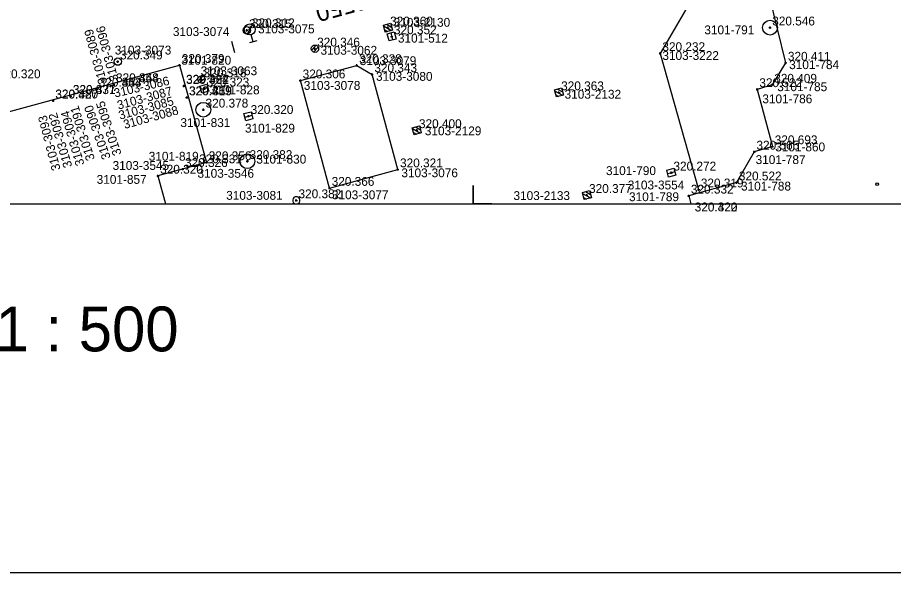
# Model space of a CAD drawing. Extents: x -821875 to -821475, y -1070280 to -1069975.
# Drawn here: x -821680.9 to -821621.5, y -1070275 to -1070237.4 of the extents above; entities that cross this region are included whole.
import ezdxf

# ---------------------------------------------------------------- set-up
doc = ezdxf.new("R2010")
doc.units = 0
for name, color, linetype in [('Vrstva 1', 7, 'Continuous'), ('Vrstva 17', 7, 'Continuous'), ('Vrstva 23', 7, 'Continuous'), ('Vrstva 3', 7, 'Continuous'), ('Vrstva 36', 7, 'Continuous'), ('Vrstva 41', 7, 'Continuous'), ('Vrstva 43', 7, 'Continuous'), ('Vrstva 47', 7, 'Continuous'), ('Vrstva 52', 7, 'Continuous'), ('Vrstva 59', 7, 'Continuous'), ('Vrstva 6', 7, 'Continuous'), ('Vrstva 60', 7, 'Continuous'), ('Vrstva 61', 7, 'Continuous'), ('Vrstva 63', 7, 'Continuous')]:
    doc.layers.add(name, color=color, linetype=linetype)

# ---------------------------------------------------------------- blocks, each defined once
blk = doc.blocks.new('BOD')
at = {"layer": 'Vrstva 3'}
for p, q in [((-0.15, 0), (0.15, 0)), ((0, -0.15), (0, 0.15))]:
    blk.add_line(p, q, dxfattribs=at)

msp = doc.modelspace()

# ---------------------------------------------------------------- linework, layer by layer
at = {"layer": 'Vrstva 1'}
for points in [[(-821475, -1069975), (-821875, -1069975), (-821875, -1070275), (-821475, -1070275)], [(-821500, -1070000), (-821850, -1070000), (-821850, -1070250), (-821500, -1070250)], [(-821500, -1070000), (-821850, -1070000), (-821850, -1070250), (-821500, -1070250)]]:
    msp.add_lwpolyline(points, close=True, dxfattribs=at)
for points in [[(-821650, -1070250), (-821650, -1070248.75), (-821650, -1070250)], [(-821651.25, -1070250), (-821650, -1070250)], [(-821650, -1070250), (-821648.75, -1070250), (-821650, -1070250)]]:
    msp.add_lwpolyline(points, dxfattribs=at)
at = {"layer": 'Vrstva 17'}
for p, q in [((-821633.688, -1070233.585), (-821637.314, -1070239.784)), ((-821637.314, -1070239.784), (-821634.707, -1070249.031))]:
    msp.add_line(p, q, dxfattribs=at)
at = {"layer": 'Vrstva 23'}
for p, q in [((-821661.733, -1070241.633), (-821657.903, -1070240.599)), ((-821657.903, -1070240.599), (-821656.866, -1070241.213)), ((-821659.762, -1070248.922), (-821661.733, -1070241.633)), ((-821655.121, -1070247.667), (-821656.866, -1070241.213)), ((-821659.762, -1070248.922), (-821655.121, -1070247.667))]:
    msp.add_line(p, q, dxfattribs=at)
for points in [[(-821618.032, -1070237.847), (-821619.404, -1070232.915), (-821629.947, -1070235.793), (-821628.796, -1070240.434), (-821629.722, -1070241.929), (-821630.734, -1070242.226), (-821629.687, -1070246.101), (-821630.928, -1070246.466), (-821632.123, -1070248.555), (-821635.379, -1070249.449), (-821635.229, -1070250)], [(-821684.746, -1070244.201), (-821684.641, -1070244.592), (-821669.935, -1070240.588), (-821668.108, -1070247.182)], [(-821668.108, -1070247.182), (-821671.404, -1070248.095), (-821670.899, -1070250)]]:
    msp.add_lwpolyline(points, dxfattribs=at)
at = {"layer": 'Vrstva 36'}
for p, q in [((-821656.086, -1070237.924), (-821655.544, -1070238.236)), ((-821655.883, -1070237.81), (-821655.548, -1070238.004)), ((-821656.013, -1070238.196), (-821655.817, -1070238.31)), ((-821660.978, -1070239.563), (-821660.654, -1070239.24)), ((-821660.848, -1070239.698), (-821660.52, -1070239.37)), ((-821668.68, -1070241.65), (-821668.356, -1070241.327)), ((-821668.55, -1070241.785), (-821668.222, -1070241.458)), ((-821644.476, -1070242.318), (-821643.934, -1070242.63)), ((-821644.273, -1070242.204), (-821643.938, -1070242.398)), ((-821644.403, -1070242.59), (-821644.207, -1070242.704)), ((-821654.128, -1070244.886), (-821653.586, -1070245.198)), ((-821654.055, -1070245.158), (-821653.859, -1070245.272)), ((-821653.925, -1070244.772), (-821653.59, -1070244.966)), ((-821642.582, -1070249.281), (-821642.04, -1070249.593)), ((-821642.379, -1070249.167), (-821642.044, -1070249.361)), ((-821642.509, -1070249.553), (-821642.313, -1070249.667))]:
    msp.add_line(p, q, dxfattribs=at)
for points in [[(-821655.618, -1070237.739), (-821655.489, -1070238.222), (-821655.972, -1070238.351), (-821656.101, -1070237.868), (-821655.618, -1070237.739)], [(-821644.008, -1070242.133), (-821643.879, -1070242.616), (-821644.362, -1070242.745), (-821644.491, -1070242.262), (-821644.008, -1070242.133)], [(-821653.66, -1070244.701), (-821653.531, -1070245.184), (-821654.014, -1070245.313), (-821654.143, -1070244.83), (-821653.66, -1070244.701)], [(-821642.114, -1070249.096), (-821641.985, -1070249.579), (-821642.468, -1070249.708), (-821642.597, -1070249.225), (-821642.114, -1070249.096)]]:
    msp.add_lwpolyline(points, dxfattribs=at)
for centre in [(-821660.747, -1070239.471), (-821668.449, -1070241.558)]:
    msp.add_circle(centre, 0.25, dxfattribs=at)
at = {"layer": 'Vrstva 41'}
for p, q in [((-821664.987, -1070237.838), (-821665.358, -1070238.49)), ((-821664.939, -1070239.012), (-821665.073, -1070238.526)), ((-821664.698, -1070238.946), (-821665.18, -1070239.078))]:
    msp.add_line(p, q, dxfattribs=at)
msp.add_circle((-821665.172, -1070238.164), 0.375, dxfattribs=at)
at = {"layer": 'Vrstva 43'}
for points in [[(-821655.602, -1070238.396), (-821655.361, -1070238.331), (-821655.232, -1070238.814), (-821655.715, -1070238.943), (-821655.844, -1070238.46), (-821655.602, -1070238.396), (-821655.474, -1070238.878)], [(-821668.011, -1070242.117), (-821667.946, -1070242.359), (-821668.43, -1070242.489), (-821668.56, -1070242.005), (-821668.076, -1070241.875), (-821668.011, -1070242.117), (-821668.495, -1070242.247)], [(-821665.504, -1070244.109), (-821665.564, -1070243.866), (-821665.078, -1070243.746), (-821664.958, -1070244.232), (-821665.444, -1070244.352), (-821665.504, -1070244.109), (-821665.018, -1070243.989)], [(-821636.322, -1070247.817), (-821636.256, -1070248.059), (-821636.739, -1070248.19), (-821636.87, -1070247.707), (-821636.387, -1070247.576), (-821636.322, -1070247.817), (-821636.804, -1070247.949)]]:
    msp.add_lwpolyline(points, dxfattribs=at)
for centre in [(-821629.859, -1070238.042), (-821668.323, -1070243.612), (-821665.334, -1070247.105)]:
    msp.add_circle(centre, 0.5, dxfattribs=at)
at = {"layer": 'Vrstva 47'}
for centre in [(-821665.373, -1070238.222), (-821674.131, -1070240.346)]:
    msp.add_circle(centre, 0.25, dxfattribs=at)
msp.add_arc((-821662.012, -1070249.761), 0.25, 287.05962, 252.94038, dxfattribs=at)
at = {"layer": 'Vrstva 52'}
msp.add_lwpolyline([(-821700.708, -1070248.976), (-821689.536, -1070245.887), (-821689.637, -1070245.511), (-821684.746, -1070244.201), (-821684.641, -1070244.592), (-821669.935, -1070240.588), (-821668.108, -1070247.182), (-821671.404, -1070248.095), (-821670.899, -1070250)], dxfattribs=at)
at = {"layer": 'Vrstva 59'}
msp.add_circle((-821622.582, -1070248.659), 0.0873, dxfattribs=at)
at = {"layer": 'Vrstva 6'}
msp.add_line((-821666.421, -1070238.967), (-821666.214, -1070239.733), dxfattribs=at)

# ---------------------------------------------------------------- block references
at = {"layer": 'Vrstva 60', "xscale": 0.5, "yscale": 0.5}
for p in [(-821665.373, -1070238.222), (-821665.172, -1070238.164), (-821655.795, -1070238.045), (-821629.859, -1070238.042), (-821655.538, -1070238.637), (-821660.747, -1070239.471), (-821637.314, -1070239.784), (-821674.131, -1070240.346), (-821669.935, -1070240.588), (-821657.903, -1070240.599), (-821628.796, -1070240.434), (-821668.449, -1070241.558), (-821661.733, -1070241.633), (-821656.866, -1070241.213), (-821675.575, -1070242.198), (-821675.572, -1070242.19), (-821674.4, -1070241.888), (-821674.399, -1070241.892), (-821669.647, -1070241.989), (-821669.644, -1070242.01), (-821668.253, -1070242.182), (-821630.734, -1070242.226), (-821629.722, -1070241.929), (-821677.333, -1070242.698), (-821677.329, -1070242.68), (-821669.453, -1070242.779), (-821669.431, -1070242.782), (-821644.185, -1070242.439), (-821678.519, -1070243.004), (-821678.518, -1070242.99), (-821668.323, -1070243.612), (-821665.261, -1070244.049), (-821653.837, -1070245.007), (-821630.928, -1070246.466), (-821629.687, -1070246.101), (-821665.334, -1070247.105), (-821669.72, -1070247.642), (-821668.758, -1070247.391), (-821668.108, -1070247.182), (-821655.121, -1070247.667), (-821671.404, -1070248.095), (-821636.563, -1070247.883), (-821659.762, -1070248.922), (-821632.123, -1070248.555), (-821642.291, -1070249.402), (-821635.379, -1070249.449), (-821634.707, -1070249.031), (-821662.012, -1070249.761)]:
    msp.add_blockref('BOD', p, dxfattribs=at)

# ---------------------------------------------------------------- texts
at = {"layer": 'Vrstva 1'}
msp.add_text('1 : 500', height=3.04, dxfattribs=at).set_placement((-821682.432, -1070260))
at = {"layer": 'Vrstva 60'}
for s, p in [('3103-2130', (-821655.404, -1070237.981)), ('3103-3074', (-821670.39, -1070238.61)), ('3103-3075', (-821664.607, -1070238.427)), ('3101-791', (-821634.315, -1070238.492)), ('3101-512', (-821655.115, -1070239.055)), ('3103-3073', (-821674.334, -1070239.863)), ('3103-3062', (-821660.368, -1070239.879)), ('3103-3222', (-821637.164, -1070240.234)), ('3101-820', (-821669.822, -1070240.553)), ('3103-3079', (-821657.705, -1070240.583)), ('3101-784', (-821628.559, -1070240.855)), ('3103-3063', (-821668.508, -1070241.269)), ('3103-3080', (-821656.604, -1070241.647)), ('3103-3078', (-821661.503, -1070242.26)), ('3101-828', (-821667.894, -1070242.568)), ('3103-2132', (-821643.802, -1070242.86)), ('3101-785', (-821629.368, -1070242.35)), ('3101-786', (-821630.379, -1070243.171)), ('3101-831', (-821669.879, -1070244.785)), ('3101-829', (-821665.498, -1070245.158)), ('3103-2129', (-821653.288, -1070245.343)), ('3101-860', (-821629.508, -1070246.435)), ('3101-819', (-821672.029, -1070247.067)), ('3101-830', (-821664.727, -1070247.264)), ('3101-787', (-821630.836, -1070247.295)), ('3103-3545', (-821674.482, -1070247.691)), ('3103-3546', (-821668.718, -1070248.224)), ('3103-3076', (-821654.88, -1070248.19)), ('3101-790', (-821640.99, -1070248.042)), ('3101-857', (-821675.562, -1070248.636)), ('3103-3554', (-821639.513, -1070249.015)), ('3101-788', (-821631.826, -1070249.092)), ('3103-3081', (-821666.773, -1070249.719)), ('3103-3077', (-821659.594, -1070249.682)), ('3103-2133', (-821647.272, -1070249.736)), ('3101-789', (-821639.427, -1070249.812))]:
    msp.add_text(s, height=0.6, dxfattribs=at).set_placement(p)
for s, rotation, p in [('3103-3096', 104.61057, (-821674.077, -1070241.589)), ('3103-3089', 105.04803, (-821674.845, -1070241.796)), ('3103-3086', 13.26534, (-821674.313, -1070242.788)), ('3103-3087', 15.2332, (-821674.08, -1070243.609)), ('3103-3085', 15.37083, (-821673.981, -1070244.291)), ('3103-3091', 107.06352, (-821675.681, -1070246.961)), ('3103-3090', 109.28724, (-821674.598, -1070246.866)), ('3103-3095', 108.13445, (-821673.866, -1070246.612)), ('3103-3088', 15.35766, (-821673.659, -1070244.916)), ('3103-3093', 104.57458, (-821678.008, -1070247.657)), ('3103-3092', 106.09021, (-821677.212, -1070247.449)), ('3103-3094', 106.10826, (-821676.388, -1070247.314))]:
    msp.add_text(s, height=0.6, rotation=rotation, dxfattribs=at).set_placement(p)
at = {"layer": 'Vrstva 61'}
for s, p in [('320.315', (-821665.223, -1070238.072)), ('320.312', (-821665.022, -1070238.014)), ('320.360', (-821655.645, -1070237.895)), ('320.546', (-821629.709, -1070237.892)), ('320.352', (-821655.388, -1070238.487)), ('320.346', (-821660.597, -1070239.321)), ('320.232', (-821637.164, -1070239.634)), ('320.349', (-821673.981, -1070240.196)), ('320.379', (-821669.785, -1070240.438)), ('320.328', (-821657.753, -1070240.449)), ('320.411', (-821628.646, -1070240.284)), ('320.343', (-821656.716, -1070241.063)), ('320.320', (-821682.27, -1070241.476)), ('320.368', (-821674.25, -1070241.738)), ('320.318', (-821668.299, -1070241.408)), ('320.306', (-821661.583, -1070241.483)), ('320.443', (-821675.425, -1070242.048)), ('320.354', (-821675.422, -1070242.04)), ('320.444', (-821674.249, -1070241.742)), ('320.324', (-821669.497, -1070241.839)), ('320.462', (-821669.494, -1070241.86)), ('320.323', (-821668.103, -1070242.032)), ('320.363', (-821644.035, -1070242.289)), ('320.522', (-821630.584, -1070242.076)), ('320.409', (-821629.572, -1070241.779)), ('320.427', (-821678.369, -1070242.854)), ('320.380', (-821678.368, -1070242.84)), ('320.431', (-821677.183, -1070242.548)), ('320.377', (-821677.179, -1070242.53)), ('320.459', (-821669.303, -1070242.629)), ('320.319', (-821669.281, -1070242.632)), ('320.378', (-821668.173, -1070243.462)), ('320.320', (-821665.111, -1070243.899)), ('320.400', (-821653.687, -1070244.857)), ('320.565', (-821630.778, -1070246.316)), ('320.693', (-821629.537, -1070245.951)), ('320.356', (-821667.958, -1070247.032)), ('320.382', (-821665.184, -1070246.955)), ('320.326', (-821669.57, -1070247.492)), ('320.331', (-821668.608, -1070247.241)), ('320.321', (-821654.971, -1070247.517)), ('320.320', (-821671.254, -1070247.945)), ('320.272', (-821636.413, -1070247.733)), ('320.366', (-821659.612, -1070248.772)), ('320.522', (-821631.973, -1070248.405)), ('320.377', (-821642.141, -1070249.252)), ('320.332', (-821635.229, -1070249.299)), ('320.319', (-821634.557, -1070248.881)), ('320.382', (-821661.862, -1070249.611)), ('320.420', (-821634.972, -1070250.512)), ('320.322', (-821634.971, -1070250.505))]:
    msp.add_text(s, height=0.6, dxfattribs=at).set_placement(p)
at = {"layer": 'Vrstva 63'}
msp.add_text('ŽP 2550', height=1.2, rotation=195.35392, dxfattribs=at).set_placement((-821654.97, -1070234.911))

doc.saveas('drawing.dxf')
